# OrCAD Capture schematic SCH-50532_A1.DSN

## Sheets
1 1. TITLE & NOTES: title: X-KTFS5600SKTEVM; rev: A; company: NXP Semiconductors; note: SCH-50532 PDF: SPF-50532; note: 6501 William Cannon Drive West; note: Austin, TX 78735-8598
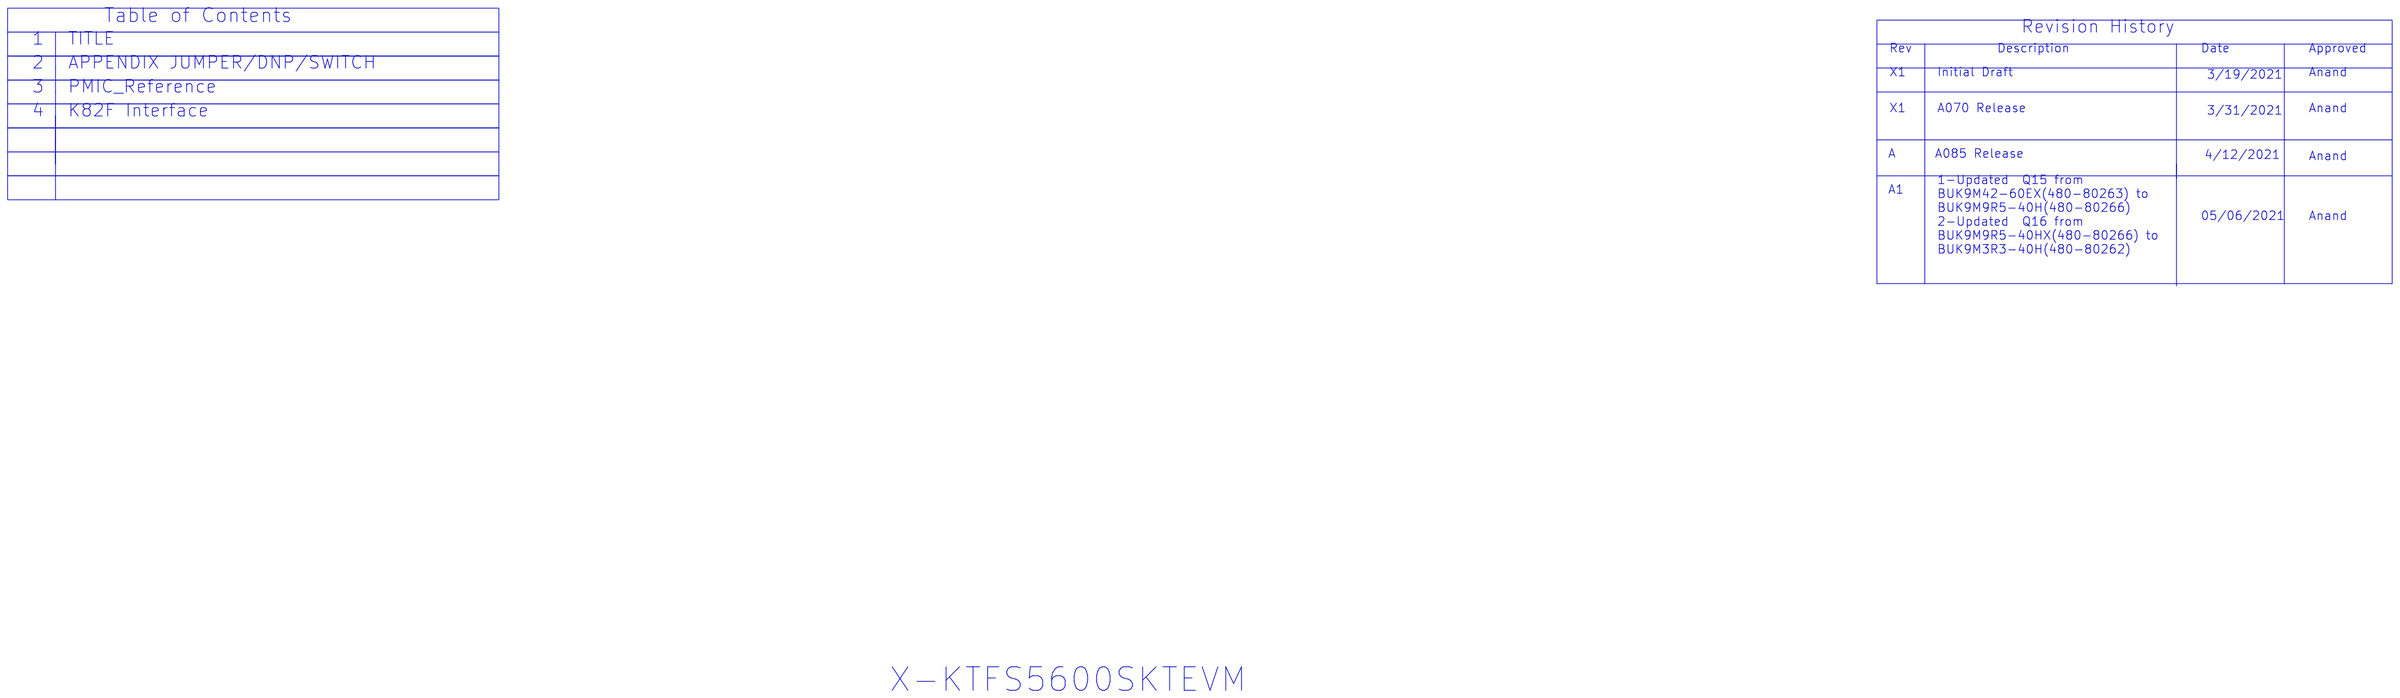
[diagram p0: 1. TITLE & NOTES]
2 3. PMIC_Reference: size D
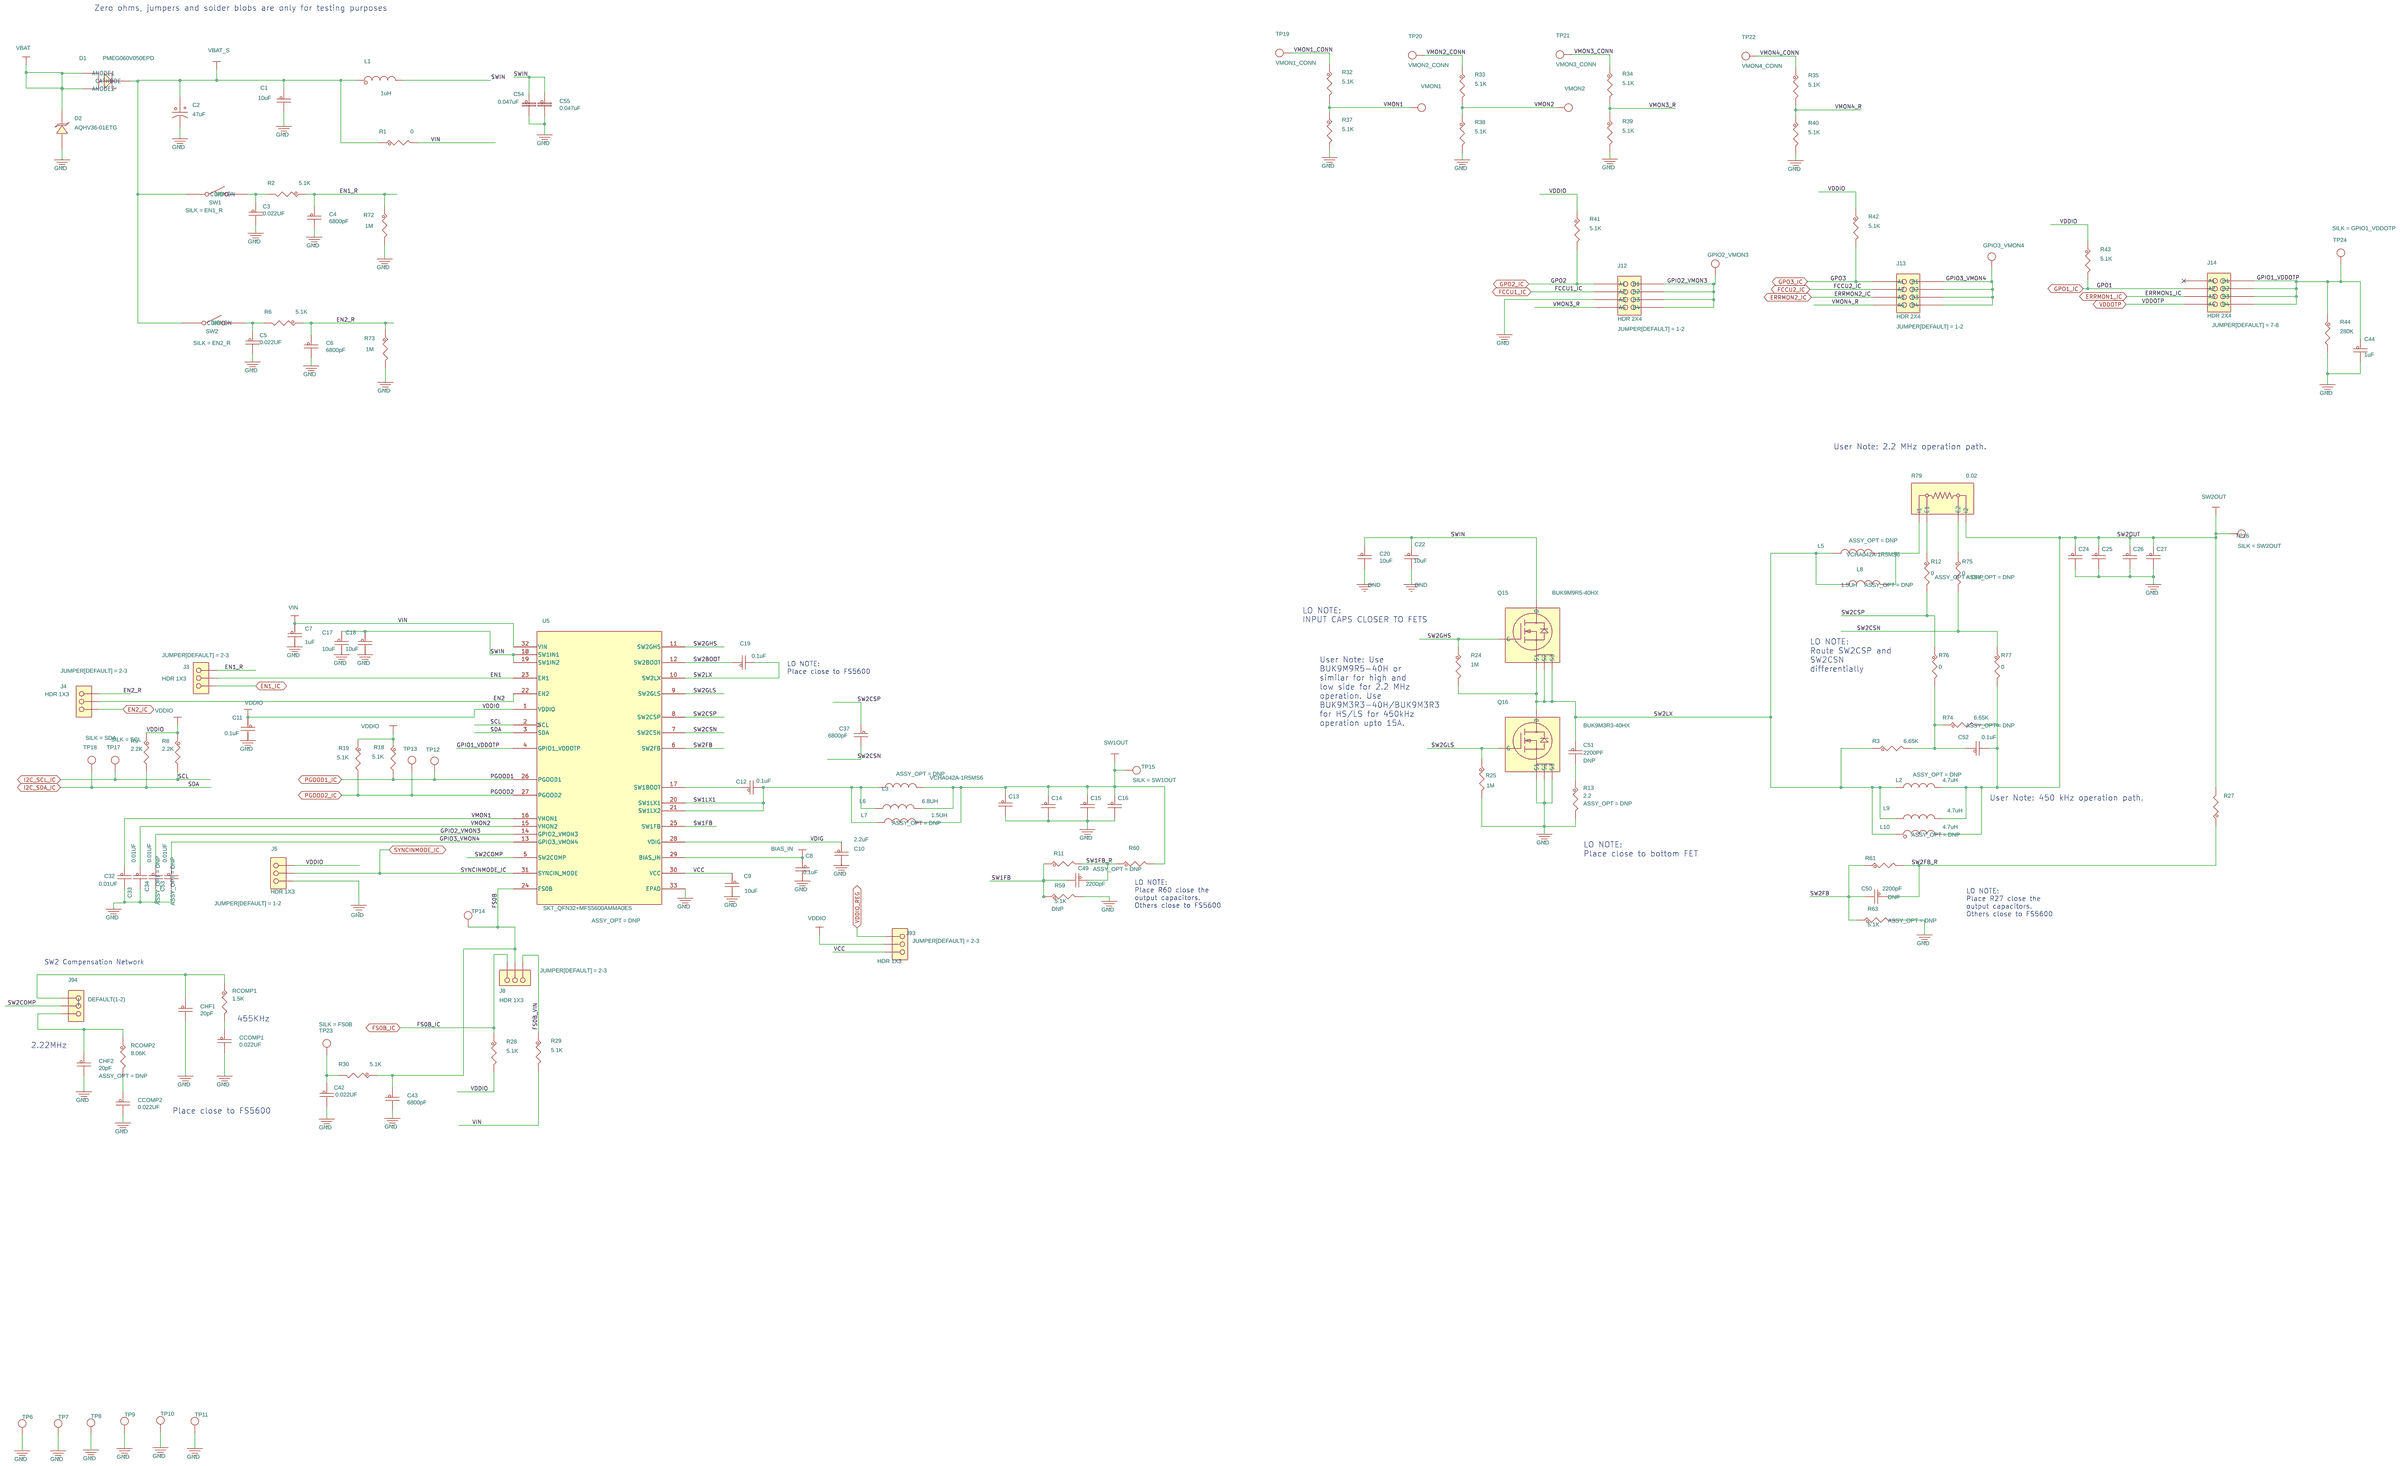
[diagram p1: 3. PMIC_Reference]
3 4. K82F Interface: size C
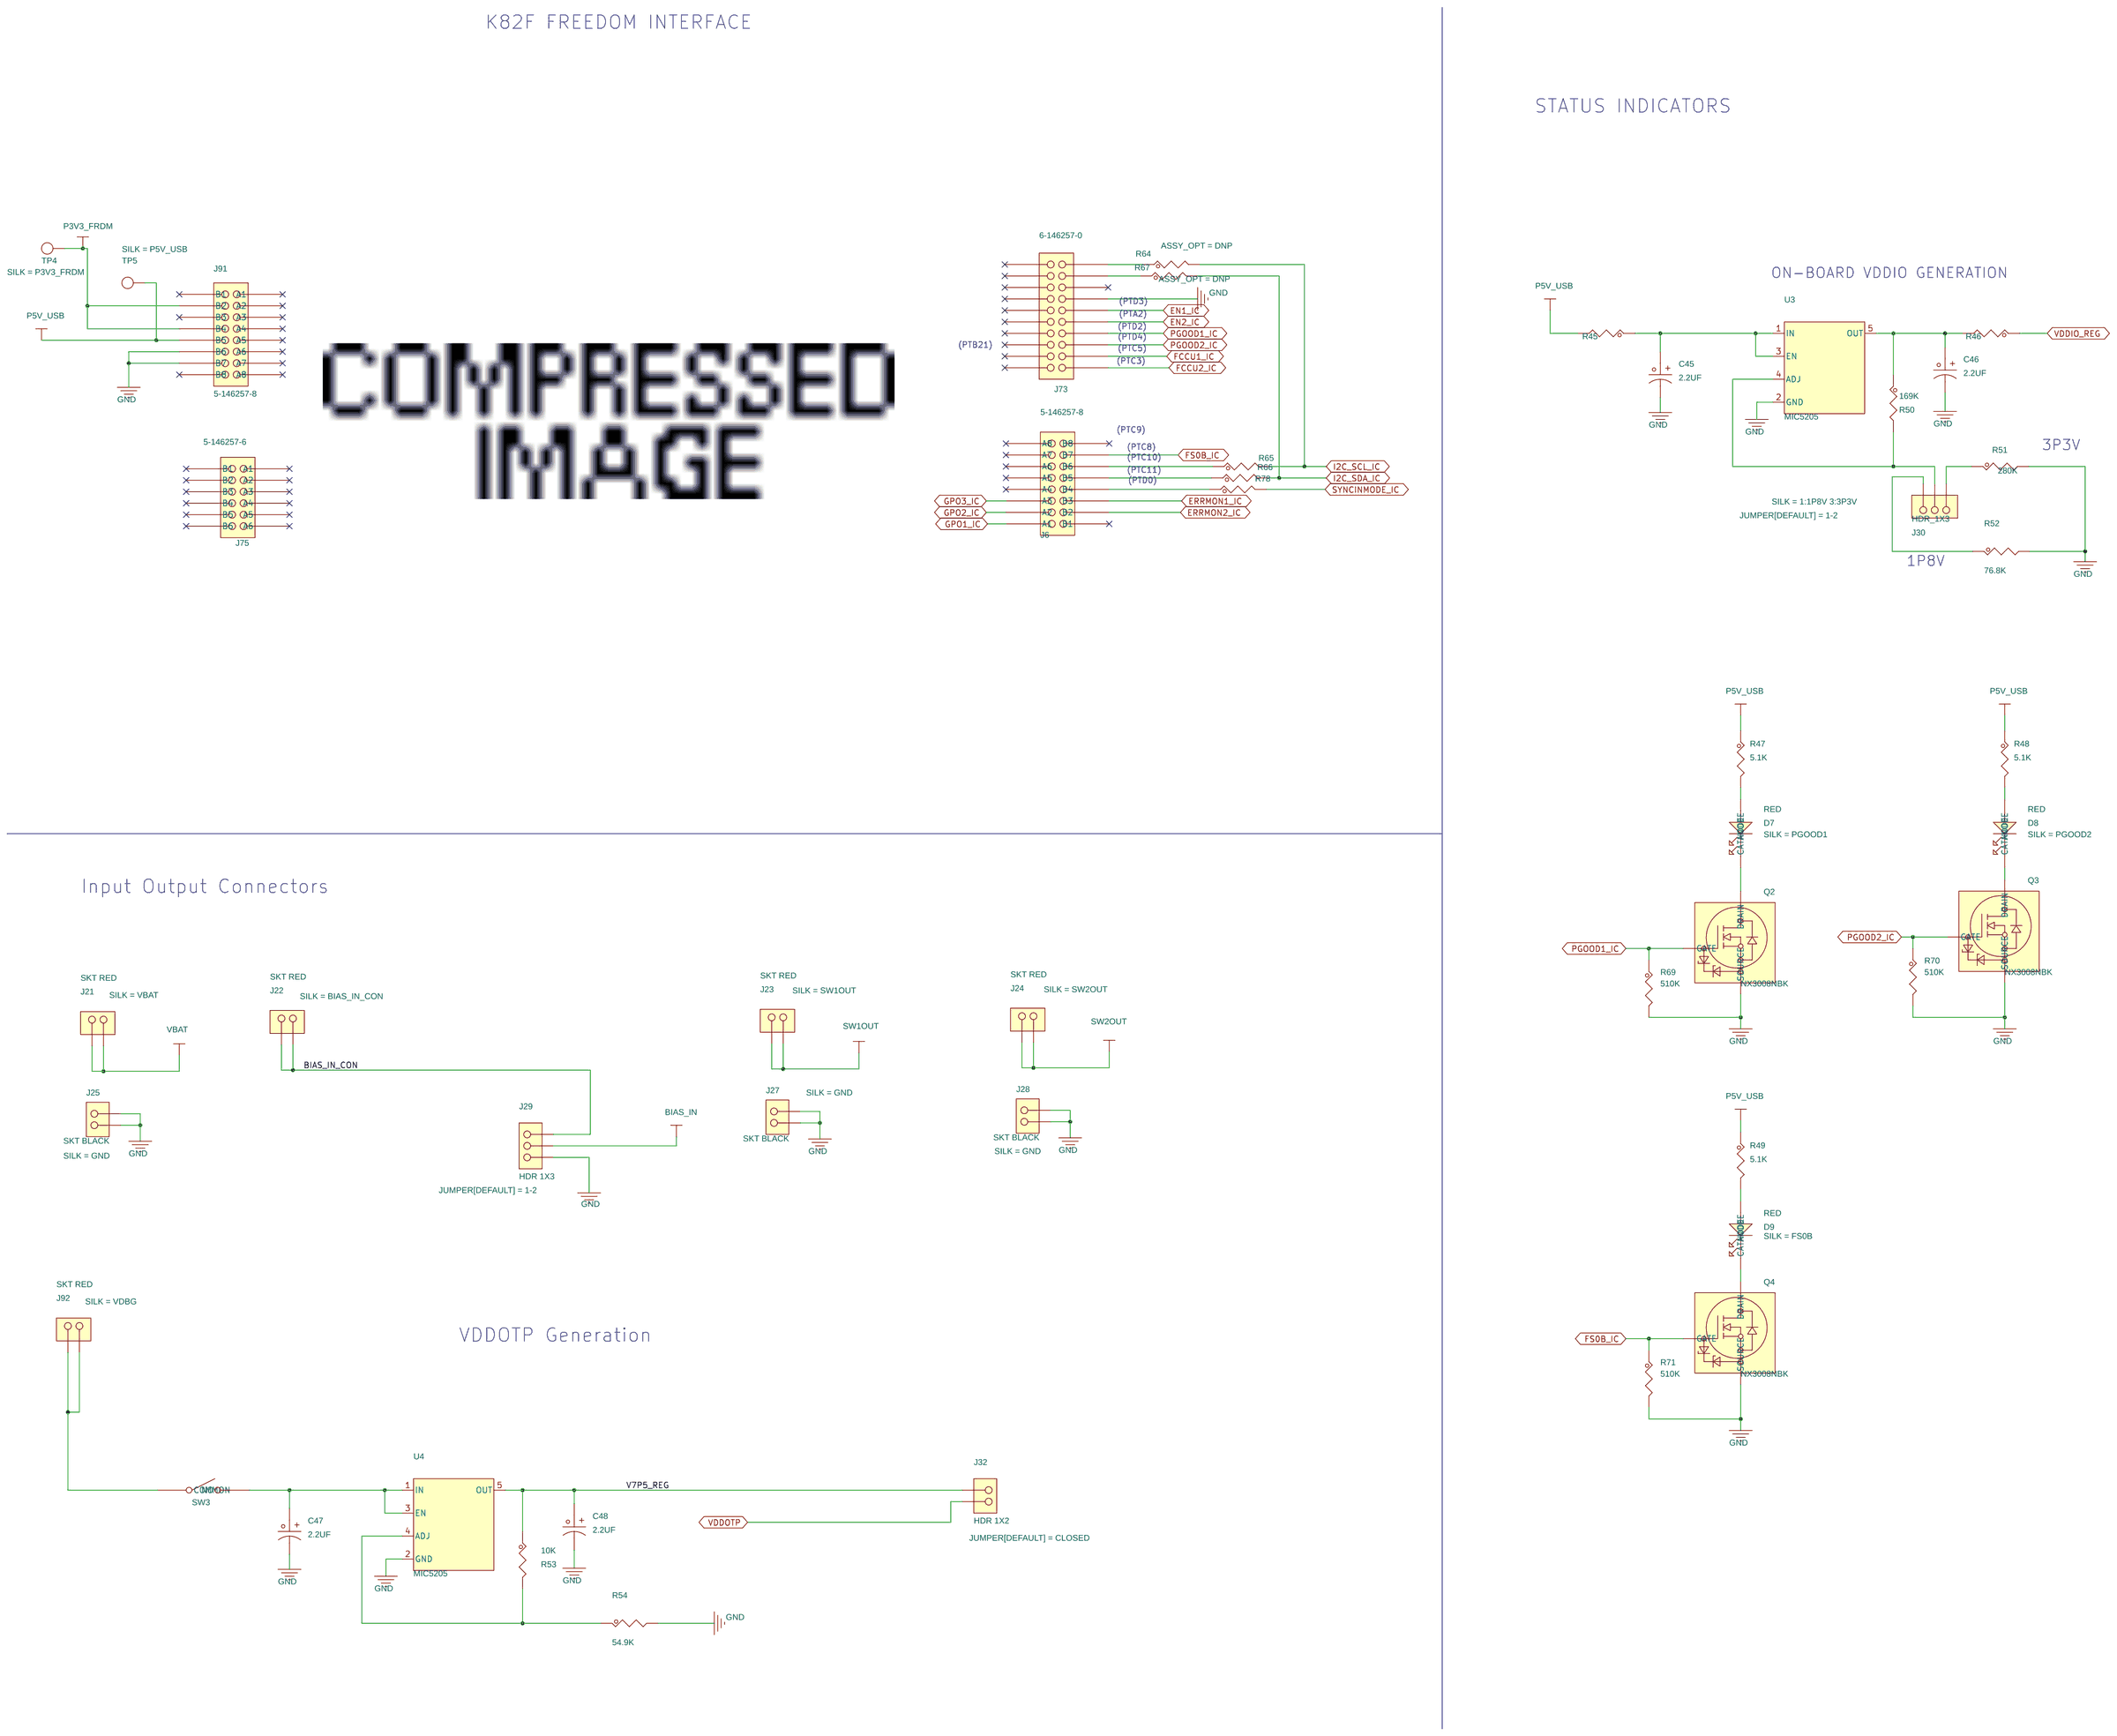
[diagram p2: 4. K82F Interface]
4 2. APPENDIX JUMPER/DNP/SWITCH
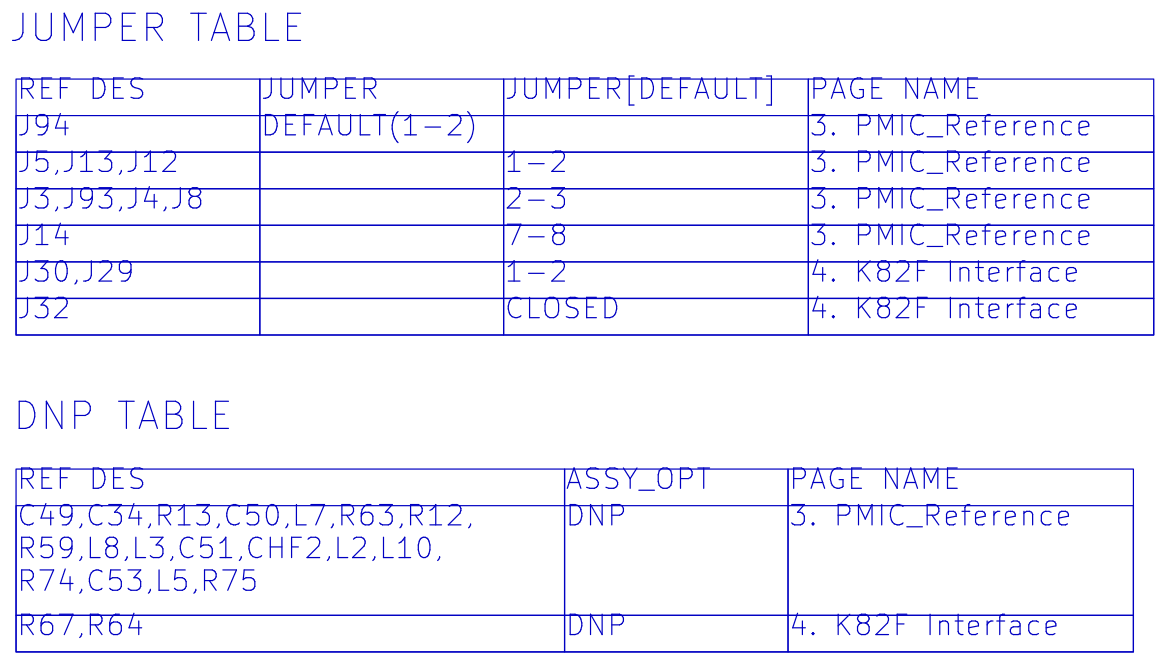
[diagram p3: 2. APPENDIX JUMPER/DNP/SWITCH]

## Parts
sheet 3. PMIC_Reference
C1  10uF  [CC1210]
C2  47uF  [cap_alel_10p5sq_smt]
C3  0.022UF  [CC1206_OV]
C4  6800pF  [CC0402_25]
C5  0.022UF  [CC1206_OV]
C6  6800pF  [CC0402_25]
C7  1uF  [cc0402_tol0p2]
C8  0.1uF  [CC0402_25]
C9  10uF  [CC1210]
C10  2.2uF  [cc0402_tol0p2]
C11  0.1uF  [CC0402_25]
C12  0.1uF  [CC0402_25]
C13  CGA6P1X7R1C226M250AC  [CC1210]
C14  CGA6P1X7R1C226M250AC  [CC1210]
C15  CGA6P1X7R1C226M250AC  [CC1210]
C16  CGA6P1X7R1C226M250AC  [CC1210]
C17  10uF  [CC1210]
C18  10uF  [CC1210]
C19  0.1uF  [CC0402_25]
C20  10uF  [CC1210]
C22  10uF  [CC1210]
C24  CGA6P1X7R1C226M250AC  [CC1210]
C25  CGA6P1X7R1C226M250AC  [CC1210]
C26  CGA6P1X7R1C226M250AC  [CC1210]
C27  CGA6P1X7R1C226M250AC  [CC1210]
C32  0.01UF  [CC0402_25]
C33  0.01UF  [CC0402_25]
C34  0.01UF  [CC0402_25]
C37  6800pF  [CC0402_25]
C42  0.022UF  [CC1206_OV]
C43  6800pF  [CC0402_25]
C44  1uF  [CC0402_25]
C49  2200pF  [CC0402_25]
C50  2200pF  [CC0402_25]
C51  2200PF  [CC0603_OV]
C52  0.1uF  [CC0603_OV]
C53  0.01UF  [CC0402_25]
C54  0.047uF  [cc0204]
C55  0.047uF  [cc0204]
CCOMP1  0.022UF  [CC0603_OV]
CCOMP2  0.022UF  [CC0603_OV]
CHF1  20pF  [CC0603_OV]
CHF2  20pF  [CC0603_OV]
D1  PMEG060V050EPD  [SOT1289]
D2  AQHV36-01ETG  [diode_sod882_sm_0p7x1p1]
GPIO2_VMON3  TPAD_030  [TPAD_030]
GPIO3_VMON4  TPAD_030  [TPAD_030]
J3  HDR 1X3  [HDR103]
J4  HDR 1X3  [HDR103]
J5  HDR 1X3  [HDR103]
J8  HDR 1X3  [HDR103]
J12  HDR 2X4  [hdr2x4_2p54_th]
J13  HDR 2X4  [hdr2x4_2p54_th]
J14  HDR 2X4  [hdr2x4_2p54_th]
J93  HDR 1X3  [HDR103]
J94  HDR 1X3  [HDR103]
L1  1uH  [ind2_7p4x6p9_sm]
L2  4.7uH  [ind2_10p9x10p4]
L3  VCHA042A-1R5MS6  [ind2_4p5x4p3]
L5  VCHA042A-1R5MS6  [ind2_4p5x4p3]
L6  6.8UH  [ind2_10p9x10p4]
L7  1.5UH  [ind_2_5p4x5p8]
L8  1.5UH  [ind_2_5p4x5p8]
L9  4.7uH  [ind2_13p4x12p9mm_sm]
L10  4.7uH  [ind2_7p4x6p9_sm]
Q15  BUK9M9R5-40HX  [lfpak33_0p65_3p4x2p7]
Q16  BUK9M3R3-40HX  [lfpak33_0p65_3p4x2p7]
R1  0  [RC0603_OV]
R2  5.1K  [RC0402_25]
R3  6.65K  [RC0402_25]
R6  5.1K  [RC0402_25]
R8  2.2K  [RC0402_25]
R9  2.2K  [RC0402_25]
R11  0  [RC0402_25]
R12  0  [RC0603_OV]
R13  2.2  [RC0805_OV]
R18  5.1K  [RC0402_25]
R19  5.1K  [RC0402_25]
R24  1M  [RC0402_25]
R25  1M  [RC0402_25]
R27  49.9  [RC0603_OV]
R28  5.1K  [RC0402_25]
R29  5.1K  [RC0402_25]
R30  5.1K  [RC0402_25]
R32  5.1K  [RC0402_25]
R33  5.1K  [RC0402_25]
R34  5.1K  [RC0402_25]
R35  5.1K  [RC0402_25]
R37  5.1K  [RC0402_25]
R38  5.1K  [RC0402_25]
R39  5.1K  [RC0402_25]
R40  5.1K  [RC0402_25]
R41  5.1K  [RC0402_25]
R42  5.1K  [RC0402_25]
R43  5.1K  [RC0402_25]
R44  280K  [RC0402_25]
R59  5.1K  [RC0402_25]
R60  49.9  [RC0603_OV]
R61  0  [RC0402_25]
R63  5.1K  [RC0402_25]
R72  1M  [RC0402_25]
R73  1M  [RC0402_25]
R74  6.65K  [RC0402_25]
R75  0  [RC0603_OV]
R76  0  [RC0603_OV]
R77  0  [RC0603_OV]
R79  0.02  [rc2512_4p_6p6x3p4]
RCOMP1  1.5K  [RC0603_OV]
RCOMP2  8.06K  [RC0603_OV]
SW1  A6S1104-H  [sw2_6p4x3p68_sm]
SW2  A6S1104-H  [sw2_6p4x3p68_sm]
TP6  TESTLOOP  [TEST_PIN_TP107]
TP7  TESTLOOP  [TEST_PIN_TP107]
TP8  TESTLOOP  [TEST_PIN_TP107]
TP9  TESTLOOP  [TEST_PIN_TP107]
TP10  TESTLOOP  [TEST_PIN_TP107]
TP11  TESTLOOP  [TEST_PIN_TP107]
TP12  TESTLOOP_BLACK  [tp_th_063]
TP13  TESTLOOP_BLACK  [tp_th_063]
TP14  TESTLOOP_BLACK  [tp_th_063]
TP15  TESTLOOP_BLACK  [tp_th_063]
TP16  TESTLOOP_BLACK  [tp_th_063]
TP17  TESTLOOP_BLACK  [tp_th_063]
TP18  TESTLOOP_BLACK  [tp_th_063]
TP19  TESTLOOP_BLACK  [tp_th_063]
TP20  TESTLOOP_BLACK  [tp_th_063]
TP21  TESTLOOP_BLACK  [tp_th_063]
TP22  TESTLOOP_BLACK  [tp_th_063]
TP23  TPAD_030  [TPAD_030]
TP24  TPAD_030  [TPAD_030]
U5  SKT_QFN32+MFS5600AMMA0ES  [skt_qfn32_0p5_28x29_sm]
VMON1  TPAD_030  [TPAD_030]
VMON2  TPAD_030  [TPAD_030]
sheet 4. K82F Interface
C45  2.2UF  [CC3216]
C46  2.2UF  [CC3216]
C47  2.2UF  [CC3216]
C48  2.2UF  [CC3216]
D7  RED  [led2_2p1x1p5_nsp]
D8  RED  [led2_2p1x1p5_nsp]
D9  RED  [led2_2p1x1p5_nsp]
J6  5-146257-8  [hdr208_197x789_th]
J21  SKT RED  [con_banana_571]
J22  SKT RED  [con_banana_571]
J23  SKT RED  [con_banana_571]
J24  SKT RED  [con_banana_571]
J25  SKT BLACK  [con_banana_571]
J27  SKT BLACK  [con_banana_571]
J28  SKT BLACK  [con_banana_571]
J29  HDR 1X3  [HDR103]
J30  HDR_1X3  [HDR103]
J32  HDR 1X2  [hdr102_338h]
J73  6-146257-0  [hdr210_197x989_th]
J75  5-146257-6  [hdr206_197x589_th]
J91  5-146257-8  [hdr208_197x789_th]
J92  SKT RED  [con_banana_571]
Q2  NX3008NBK  [SOT23_A]
Q3  NX3008NBK  [SOT23_A]
Q4  NX3008NBK  [SOT23_A]
R45  0  [RC0402_25]
R46  0  [RC0402_25]
R47  5.1K  [RC0402_25]
R48  5.1K  [RC0402_25]
R49  5.1K  [RC0402_25]
R50  169K  [RC0402_25]
R51  280K  [RC0402_25]
R52  76.8K  [RC0402_25]
R53  10K  [RC0402_25]
R54  54.9K  [RC0402_25]
R64  0  [RC0402_25]
R65  0  [RC0402_25]
R66  0  [RC0402_25]
R67  0  [RC0402_25]
R69  510K  [RC0603_OV]
R70  510K  [RC0603_OV]
R71  510K  [RC0603_OV]
R78  0  [RC0402_25]
SW3  A6S1104-H  [sw2_6p4x3p68_sm]
TP4  TPAD_030  [TPAD_030]
TP5  TPAD_030  [TPAD_030]
U3  MIC5205  [sot23-20x60-5]
U4  MIC5205  [sot23-20x60-5]

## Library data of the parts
C1 C9 C17 C18 C20 C22 = CAP_NP: CAP CER 10uF 50V 10% X7S AEC-Q200 1210; AGILE_PN: 150-79213; CAD_APPROVED: Yes; FPLIST: CC1210,1210_CC; HEIGHT: 2.8MM; MFG_NAME01: MURATA; MFG_PN01: GCM32EC71H106KA03; Package Size: 1210; ROHS: Yes; Tolerance: 10%; VOLTAGE: 50V
C2 = CAP_POL: CAP ALEL 47uF 50V 20% AEC-Q200 SMD; AGILE_PN: 150-79431; CAD_APPROVED: Yes; HEIGHT: 10.5MM; MFG_NAME01: VISHAY INTERTECHNOLOGY; MFG_PN01: MAL214699101E3; ROHS: Yes; Tolerance: 20%; VOLTAGE: 50V
C3 C5 C42 = CAP_NP: CAP CER 0.022UF 100V 10% X7R 1206; AGILE_PN: 150-76992; CAD_APPROVED: Yes; FPLIST: CC1206_OV,CC1206,1206_CC; HEIGHT: 0.94MM; MFG_NAME01: AVX; MFG_PN01: 12061C223KAT2A; Package Size: 1206; ROHS: Yes; Tolerance: 10%; VOLTAGE: 100V
C4 C6 C37 C43 = CAP_NP: CAP CER 6800PF 50V 10% X7R 0402; AGILE_PN: 150-77502; CAD_APPROVED: Yes; FPLIST: CC0402_25,CC0402_HD,0402_CC; HEIGHT: 0.55 MM; MFG_NAME01: KEMET; MFG_PN01: C0402C682K5RAC_; Package Type: 0402; ROHS: Yes; Tolerance: 10%; VOLTAGE: 50V
C7 = CAP_NP: CAP CER 1uF 10V 10% X7S AEC-Q200 0402; AGILE_PN: 150-79497; CAD_APPROVED: Yes; FPLIST: CC0402_25,CC0402_HD,0402_CC; HEIGHT: 0.7MM; MFG_NAME01: MURATA; MFG_PN01: GCM155C71A105KE38D; Package Size: 0402; ROHS: Yes; Tolerance: 10%; VOLTAGE: 10V
C8 C11 = CAP_NP: CAP CER 0.1uF 50V 10% X7R AEC-Q200 0402; AGILE_PN: 150-79461; CAD_APPROVED: Yes; FPLIST: CC0402_25,CC0402_HD,0402_CC; HEIGHT: 0.55MM; MFG_NAME01: MURATA; MFG_PN01: GCM155R71H104KE02D; Package Size: 0402; ROHS: Yes; Tolerance: 10%; VOLTAGE: 50V
C10 = CAP_NP: CAP CER 2.2uF 10V 10% X7S AEC-Q200 0402; AGILE_PN: 150-79885; CAD_APPROVED: Yes; FPLIST: CC0402_25,CC0402_HD,0402_CC; HEIGHT: 0.7MM; MFG_NAME01: MURATA; MFG_PN01: GRT155C71A225KE13; ROHS: Yes; Temp Range: -55°C to +125°C; Tolerance: 10%; VOLTAGE: 10 V
C12 C19 = CAP_NP: CAP CER 0.1uF 50V 10% X7R AEC-Q200 0402; AGILE_PN: 150-79461; CAD_APPROVED: Yes; FPLIST: CC0402_25,CC0402_HD,0402_CC,CC0402_18; HEIGHT: 0.55MM; MFG_NAME01: MURATA; MFG_PN01: GCM155R71H104KE02D; Package Size: 0402; ROHS: Yes; Tolerance: 10%; VOLTAGE: 50V
C13-C16 C24-C27 = CAP_NP: CAP CER 22uF 16V 20% X7R AEC-Q200 1210; AGILE_PN: 150-80303; CAD_APPROVED: Yes; FPLIST: CC1210,1210_CC; HEIGHT: 2.8MM; MFG_NAME01: TDK; Package Type: 1210; ROHS: Yes; Temp Range: &#8722;55°C to +125°C; Tolerance: 10%; VOLTAGE: 16V
C32 C33 = CAP_NP: CAP CER 0.01UF 10V 20% X7R 0402; AGILE_PN: 150-30081; CAD_APPROVED: Yes; FPLIST: CC0402_25,CC0402_HD,0402_CC,capc0402_l; HEIGHT: 0.56 MM; MFG_NAME01: AVX; MFG_PN01: 0402ZC103MAT2A; Package Size: 0402; ROHS: Yes; Tolerance: 20%; VOLTAGE: 10V
C34 C53 = CAP_NP: CAP CER 0.01UF 10V 20% X7R 0402; AGILE_PN: 150-30081; ASSY_OPT: DNP; CAD_APPROVED: Yes; FPLIST: CC0402_25,CC0402_HD,0402_CC,capc0402_l; HEIGHT: 0.56 MM; MFG_NAME01: AVX; MFG_PN01: 0402ZC103MAT2A; Package Size: 0402; ROHS: Yes; Tolerance: 20%; VOLTAGE: 10V
C44 = CAP_NP: CAP CER 1.0uF 16V 10% X6S 0402; AGILE_PN: 150-80262; CAD_APPROVED: Yes; FPLIST: CC0402_25,CC0402_HD,0402_CC; HEIGHT: 0.55MM; MFG_NAME01: MURATA; MFG_PN01: GRM155C81C105KE11D; ROHS: Yes; Temp Range: -55°C to +105°C; Temp_Range: -55°C to +105°C; Tolerance: 10%; VOLTAGE: 16V
C49 C50 = CAP_NP: CAP CER 2200pF 50V 10% X7R AEC-Q200 0402; AGILE_PN: 150-79020; ASSY_OPT: DNP; CAD_APPROVED: Yes; FPLIST: CC0402_25,CC0402_HD,0402_CC; HEIGHT: 0.55MM; MFG_NAME01: MURATA; MFG_PN01: GCM155R71H222KA37D; Package Size: 0402; Package Type: ø180mm Reel PAPER; ROHS: Yes; Tolerance: 10%; VOLTAGE: 50V
C51 = CAP_NP: CAP CER 2200PF 50V 10% X7R 0603; AGILE_PN: 150-75275; ASSY_OPT: DNP; CAD_APPROVED: Yes; FPLIST: CC0603_OV,CC0603,0603_CC; HEIGHT: 0.9652MM; MFG_NAME01: AVX; MFG_PN01: 06035C222KAT2A; Package Size: 0603; Package Type: paper tape; ROHS: Yes; Tolerance: 10%; VOLTAGE: 50V
C52 = CAP_NP: CAP CER 0.1uF 50V 5% X7R AEC-Q200 0603; AGILE_PN: 150-79363; CAD_APPROVED: Yes; HEIGHT: 0.87MM; MFG_NAME01: KEMET; MFG_PN01: C0603C104J5RACAUTO; Package Size: 0603; Package Type: 7" Reel; ROHS: Yes; Temp Range: -55°C to +125°C; Tolerance: 5%; VOLTAGE: 50V
C54 C55 = CAP_NP_RVRS: CAP CER 0.047 uF 50V 20% X7R AEC-Q200 0204; AGILE_PN: 180-81030; CAD_APPROVED: Yes; HEIGHT: 0.35MM; MFG_NAME01: TDK Corporation; MFG_PN01: CGAEA1X7R1H473M030BC; Package Size: 0204 (0510 Metric); Package Type: Surface Mount, MLCC; ROHS: yes; Rated Voltage: 50V; Tolerance: 20%; VOLTAGE: 50V
CCOMP1 CCOMP2 = CAP_NP: CAP CER 0.022UF 50V 5% X7R 0603; AGILE_PN: 150-77536; CAD_APPROVED: Yes; FPLIST: CC0603_OV,CC0603,0603_CC; HEIGHT: 0.9MM; MFG_NAME01: KEMET; MFG_PN01: C0603C223J5RACTU; Package Size: 0603; ROHS: Yes; Tolerance: 5%; VOLTAGE: 50V
CHF1 = CAP_NP: CAP CER 20pF 50V C0G 1% 0603; AGILE_PN: 150-80878; CAD_APPROVED: Yes; FPLIST: CC0603_OV,CC0603,0603_CC; HEIGHT: 0.87MM; MFG_NAME01: KEMET; MFG_PN01: C0603C200F5GACTU; Package Size: 0603 (1608 metric); Package Type: SMD/SMT; ROHS: Yes; Rated Voltage: 50VDC; Temp Range: -55 °C to +125 °C; Tolerance: 1%
CHF2 = CAP_NP: CAP CER 20pF 50V C0G 1% 0603; AGILE_PN: 150-80878; ASSY_OPT: DNP; CAD_APPROVED: Yes; FPLIST: CC0603_OV,CC0603,0603_CC; HEIGHT: 0.87MM; MFG_NAME01: KEMET; MFG_PN01: C0603C200F5GACTU; Package Size: 0603 (1608 metric); Package Type: SMD/SMT; ROHS: Yes; Rated Voltage: 50VDC; Temp Range: -55 °C to +125 °C; Tolerance: 1%
D1 = DIODE_SCH_A1A2C3: DIODE SCH RECT 60V 5A AEC-Q101 SOT1289; AGILE_PN: 480-78888; CAD_APPROVED: Yes; HEIGHT: 0.82MM; MFG_NAME01: NEXPERIA; ROHS: Yes; VOLTAGE: 60V
D2 = DIODE_TVS: DIODE TVS UNIDIR 36V -- AEC-Q101 SOD882; AGILE_PN: 480-80142; CAD_APPROVED: Yes; HEIGHT: 0.6MM; MFG_NAME01: LITTELFUSE; REQUESTED_COMPLETION_DATE: Not an expedite request; ROHS: Yes; Temp Range: -40C to +150C; Temp_Range: -40C to +150C
GPIO2_VMON3 GPIO3_VMON4 VMON1 VMON2 = TestLoop: TEST POINT PAD 30MIL DIA SMT, NO PART TO ORDER; 3D_Mechanical_Footprint_File: ftp://fcl.am.freescale.net/ALLEGRO/step/tpad_030.STEP; AGILE_PN: 211-76642; CAD_APPROVED: Yes; HEIGHT: 0.1MM; MFG_NAME01: NOTACOMPONENT; MFG_PN01: NOTACOMPONENT; ROHS: Yes
J3 J4 J8 J93 = CONN_HDR_3X1: HDR 1x3 TH 100MIL SP 343H SN 100L; AGILE_PN: 210-80334; CAD_APPROVED: Yes; HEIGHT: 8.72MM; JUMPER[DEFAULT]: 2-3; MFG_NAME01: SAMTEC; MFG_PN01: TSW-103-07-T-S; ROHS: Yes
J5 J29 = CONN_HDR_3X1: HDR 1x3 TH 100MIL SP 343H SN 100L; AGILE_PN: 210-80334; CAD_APPROVED: Yes; HEIGHT: 8.72MM; JUMPER[DEFAULT]: 1-2; MFG_NAME01: SAMTEC; MFG_PN01: TSW-103-07-T-S; ROHS: Yes
J12 J13 = CONN_HDR_4X2: HDR 2X4 TH 100MIL CTR 344H AU 118L; 3D_Mechanical_Footprint_File: ftp://fcl.am.freescale.net/ALLEGRO/step/hdr2x4_2p54_th.STEP; AGILE_PN: 210-81937; CAD_APPROVED: Yes; HEIGHT: 8.74MM; JUMPER[DEFAULT]: 1-2; MFG_NAME01: WURTH ELEKTRONIK EISOS GMBH & CO. KG (ELECTRONIC & ELECTROMEHANICAL COMP); MFG_PN01: 61300821121; Package Type: TH; ROHS: Yes; Temp Range: -40 to 105C
J14 = CONN_HDR_4X2: HDR 2X4 TH 100MIL CTR 344H AU 118L; 3D_Mechanical_Footprint_File: ftp://fcl.am.freescale.net/ALLEGRO/step/hdr2x4_2p54_th.STEP; AGILE_PN: 210-81937; CAD_APPROVED: Yes; HEIGHT: 8.74MM; JUMPER[DEFAULT]: 7-8; MFG_NAME01: WURTH ELEKTRONIK EISOS GMBH & CO. KG (ELECTRONIC & ELECTROMEHANICAL COMP); MFG_PN01: 61300821121; Package Type: TH; ROHS: Yes; Temp Range: -40 to 105C
J94 = CONN_HDR_3X1: HDR 1x3 TH 100MIL SP 343H SN 100L; AGILE_PN: 210-80334; CAD_APPROVED: Yes; HEIGHT: 8.72MM; JUMPER: DEFAULT(1-2); MFG_NAME01: SAMTEC; MFG_PN01: TSW-103-07-T-S; ROHS: Yes
L1 = INDP: IND PWR 1.0uH@100KHz 17.9A 20% AEC-Q200 SMD; AGILE_PN: 180-78579; CAD_APPROVED: Yes; HEIGHT: 4.5MM; MFG_NAME01: TDK; MFG_PN01: SPM6545VT-1R0M-D; PART_TYPE: INDUCTOR\POWER; ROHS: Yes; Temp Range: -55ºC ~ +150ºC; Temp_Range: -55ºC ~ +150ºC; Tolerance: 20%
L2 = INDUCTOR: IND PWR  4.7uH@100KHz 19.3A 20% AEC-Q200 SMD; 3D_Mechanical_Footprint_File: ftp://fcl.am.freescale.net/ALLEGRO/step/ind2_10p9x10p4.STEP; AGILE_PN: 180-78581; ASSY_OPT: DNP; CAD_APPROVED: Yes; HEIGHT: 6.5MM; MFG_NAME01: TDK; MFG_PN01: SPM10065VT-4R7M-D; ROHS: Yes; Temp Range: -55C to 150C
L3 L5 = INDUCTOR: IND PWR 1.5uH@100kHZ 7.3A 20% AEC-Q200 SMD; AGILE_PN: 180-78991; ASSY_OPT: DNP; CAD_APPROVED: Yes; HEIGHT: 2.1 MM; MFG_NAME01: CYNTEC; PART_TYPE: INDUCTOR\POWER; ROHS: Yes; Temp Range: -55 to 165 C; Tolerance: 20%
L6 = INDUCTOR: IND PWR  6.8uH@100KHz 10.2A 20% AEC-Q200 SMT; 3D_Mechanical_Footprint_File: ftp://fcl.am.freescale.net/ALLEGRO/step/ind2_10p9x10p4.STEP; AGILE_PN: 180-79064; CAD_APPROVED: Yes; HEIGHT: 6.5MM; MFG_NAME01: TDK; MFG_PN01: SPM10065VT-6R8M-D; Package Size: 10.9x10.4x6.5 mm; ROHS: Yes; Temp Range: -55°C to +155°C
L7 L8 = INDUCTOR: IND PWR 1.5UH@100kHZ 7.9A 20% AEC-Q200 SMT; 3D_Mechanical_Footprint_File: ftp://fcl.am.freescale.net/ALLEGRO/step/ind2_5p9x5p4_3_sm.STEP; AGILE_PN: 180-79063; ASSY_OPT: DNP; CAD_APPROVED: Yes; HEIGHT: 3.0MM; MFG_NAME01: TDK Corporation; MFG_PN01: SPM5030VT-1R5M-D; ROHS: Yes; Temp Range: -55ºC ~ +155ºC
L9 = INDUCTOR: IND PWR 4.7uH@100KHz 14.0A 20% AEC-Q200 SMT; AGILE_PN: 180-79532; CAD_APPROVED: Yes; HEIGHT: 6.5MM; MFG_NAME01: TDK Corporation; MFG_PN01: SPM12565VT-4R7M-D; ROHS: Yes; Temp Range: -55C to +155C
L10 = INDP: IND PWR 4.7uH@100kHz 10.9A 20% AEC-Q200 SMT; AGILE_PN: 180-78917; ASSY_OPT: DNP; CAD_APPROVED: Yes; HEIGHT: 4.5 MM; MFG_NAME01: TDK; MFG_PN01: SPM6545VT- 4R7M-D; ROHS: Yes; Temp Range: -55ºC to +155ºC
Q15 = NMOS_5P: TRAN NMOS PWR 40A 40V 9.5mOHM AEC-Q101 LFPAK33; AGILE_PN: 480-80266; CAD_APPROVED: YES; HEIGHT: 0.9MM; MFG_NAME01: Nexperia USA Inc.; Package Size: SOT-1210, 8-LFPAK33 (5-Lead); ROHS: YES; Rated Power: 55W (Ta); Temp Range: -55°C ~ +175°C
Q16 = NMOS_5P: TRAN NMOS PWR 40V 80A AEC-Q101 LFPAK33; AGILE_PN: 480-80262; CAD_APPROVED: Yes; HEIGHT: 0.9MM; MFG_NAME01: Nexperia; Package Size: SOT-1210, 8-LFPAK33 (5-Lead); ROHS: Yes; Rated Power: 101W (Ta); Temp Range: -55C to +175C
R1 = RES: RES MF ZERO OHM 1/10W -- 0603; AGILE_PN: 470-80866; CAD_APPROVED: Yes; FPLIST: RC0603_OV,RC0603,R603-X2,0603_CC; HEIGHT: 0.6MM; MFG_NAME01: YAGEO AMERICA; MFG_PN01: RC0603FR-070RL; ROHS: Yes; Temp Range: –55 °C to +155 °C; Temp_Range: –55 °C to +155 °C
R2 R6 R18 R19 R28-R30 R32-R35 R37-R43 R47-R49 = RES: RES MF 5.1K 1/16W 0.1% 0402; AGILE_PN: 470-80361; CAD_APPROVED: Yes; FPLIST: RC0603_OV,RC0603,0603_CC; HEIGHT: 0.4MM; MFG_NAME01: PANASONIC; MFG_PN01: ERA2AEB512X; ROHS: Yes; TOL: 5%; Tolerance: 0.1%
R3 = RES: RES MF 6.65K 1/16W 1% 0402; AGILE_PN: 470-82718; CAD_APPROVED: Yes; FPLIST: RC0402_25,RC0402_HD,0402_CC; HEIGHT: 0.35 MM; MFG_NAME01: Vishay / Dale; MFG_PN01: CRCW04026K65FKEDC; Package Type: PCB Mount; ROHS: Yes; Temp Range: -55°C ~ 155°C; Tolerance: 1%
R8 R9 = RES: RES MF 2.2K 1/10W 1% AEC-Q200 0402; AGILE_PN: 470-82015; CAD_APPROVED: Yes; FPLIST: RC0402_25,RC0402_HD,0402_CC; HEIGHT: 0.4MM; MFG_NAME01: KOA SPEER; MFG_PN01: RK73H1ETTP2201F; ROHS: Yes; TOL: 5%; Temp Coefficient - ppm/K: 100 ppm/K; Temp Range: -55C to +155C; Tolerance: 1%; VOLTAGE: 50V
R11 R45 R46 R61 R65 R66 R78 = RES: RES MF ZERO OHM 1/16W -- AEC-Q200 0402; AGILE_PN: 470-80742; CAD_APPROVED: Yes; FPLIST: RC0402_25,RC0402_HD,0402_CC; HEIGHT: 0.45 MM; MFG_NAME01: VISHAY INTERTECHNOLOGY; MFG_PN01: CRCW04020000Z0ED; ROHS: Yes
R12 R75 = RES: RES MF ZERO OHM 1/10W -- 0603; AGILE_PN: 470-80866; ASSY_OPT: DNP; CAD_APPROVED: Yes; FPLIST: RC0603_OV,RC0603,R603-X2,0603_CC; HEIGHT: 0.6MM; MFG_NAME01: YAGEO AMERICA; MFG_PN01: RC0603FR-070RL; ROHS: Yes; Temp Range: –55 °C to +155 °C
R13 = RES: RES MF 2.2 OHM 1/3W 5% AEC-Q200 0805; AGILE_PN: 470-80816; ASSY_OPT: DNP; CAD_APPROVED: Yes; HEIGHT: 0.6MM; MFG_NAME01: VISHAY INTERTECHNOLOGY; MFG_PN01: CRCW08052R20JNEAHP; ROHS: Yes; Tolerance: 5%
R24 R25 R72 R73 = RES: RES MF 1.0M 1/16W 1% AEC-Q200 0402; AGILE_PN: 470-30000; CAD_APPROVED: Yes; FPLIST: RC0402_25,RC0402_HD,0402_CC; HEIGHT: 0.4MM; MFG_NAME01: VISHAY INTERTECHNOLOGY; MFG_PN01: CRCW04021M00FKED; PRIORITY_PN: 006-00757; ROHS: Yes; Temp Coefficient - ppm/K: ±100ppm/°C; Temp Range: -55°C ~ 155°C; Temp_Range: -55°C ~ 155°C; Tolerance: 1%; VOLTAGE: 50V
R27 R60 = RES: RES MF 49.9 OHM 1/10W 1% 0603; AGILE_PN: 470-75432; CAD_APPROVED: Yes; FPLIST: RC0603_OV,RC0603,0603_CC; HEIGHT: 0.55 MM; MFG_NAME01: BOURNS; MFG_PN01: CR0603-FX-49R9ELF; ROHS: Yes; Tolerance: 1%
R44 R51 = RES: RES MF 280K 1/10W 1% AEC-Q200 0402; AGILE_PN: 470-31109; CAD_APPROVED: Yes; FPLIST: RC0402_25,RC0402_HD,0402_CC; HEIGHT: 0.40 MM; MFG_NAME01: KOA SPEER; MFG_PN01: RK73H1ETTP2803F; ROHS: Yes; Temp Coefficient - ppm/K: 100 ppm/K; Temp Range: -55C to +155C; Temp_Range: -55C to +155C; Tolerance: 1%; VOLTAGE: 50V
R59 R63 = RES: RES MF 5.1K 1/16W 0.1% 0402; AGILE_PN: 470-80361; ASSY_OPT: DNP; CAD_APPROVED: Yes; FPLIST: RC0603_OV,RC0603,0603_CC; HEIGHT: 0.4MM; MFG_NAME01: PANASONIC; MFG_PN01: ERA2AEB512X; ROHS: Yes; TOL: 5%; Tolerance: 0.1%
R74 = RES: RES MF 6.65K 1/16W 1% 0402; AGILE_PN: 470-82718; ASSY_OPT: DNP; CAD_APPROVED: Yes; FPLIST: RC0402_25,RC0402_HD,0402_CC; HEIGHT: 0.35 MM; MFG_NAME01: Vishay / Dale; MFG_PN01: CRCW04026K65FKEDC; Package Type: PCB Mount; ROHS: Yes; Temp Range: -55°C ~ 155°C; Tolerance: 1%
R76 R77 = RES: RES MF ZERO OHM 1/10W -- 0603; AGILE_PN: 470-80866; CAD_APPROVED: Yes; FPLIST: RC0603_OV,RC0603,R603-X2,0603_CC; HEIGHT: 0.6MM; MFG_NAME01: YAGEO AMERICA; MFG_PN01: RC0603FR-070RL; ROHS: Yes; Temp Range: –55 °C to +155 °C
R79 = RES_4PIN: RES MF 0.02 OHM 1W 1% AEC-Q200 2512; AGILE_PN: 470-82632; CAD_APPROVED: Yes; HEIGHT: 0.9MM; MFG_NAME01: VISHAY; MFG_PN01: WSK2512R0200FEA; Package Size: 2512; Package Type: SMD/SMT; ROHS: Yes; Temp Range: -65C to +170C; Tolerance: 1%
RCOMP1 = RES: RES MF 1.5K 1/10W 5% 0603; AGILE_PN: 470-75995; CAD_APPROVED: YES; FPLIST: RC0603_OV,RC0603,0603_CC; HEIGHT: 0.55 MM; MFG_NAME01: BOURNS; MFG_PN01: CR0603-JW-152ELF; ROHS: Yes; Tolerance: 5%
RCOMP2 = RES: RES MF 8.06K 1/10W 1% AEC-Q200 0603; AGILE_PN: 470-81280; CAD_APPROVED: Yes; FPLIST: RC0603_OV,RC0603,0603_CC; HEIGHT: 0.55MM; MFG_NAME01: KOA SPEER; MFG_PN01: RK73H1JTTD8061F; ROHS: Yes; Temp Range: -55°C to +155°C; Tolerance: 1%
SW1 = SW2P: SW SPST DIP SLD 25mA 24V SMD; AGILE_PN: 510-78107; CAD_APPROVED: Yes; HEIGHT: 4.5MM; MFG_NAME01: OMRON; MFG_PN01: A6S-1104-H; ROHS: Yes; SILK: EN1_R; VOLTAGE: 24V
SW2 = SW2P: SW SPST DIP SLD 25mA 24V SMD; AGILE_PN: 510-78107; CAD_APPROVED: Yes; HEIGHT: 4.5MM; MFG_NAME01: OMRON; MFG_PN01: A6S-1104-H; ROHS: Yes; SILK: EN2_R; VOLTAGE: 24V
TP6-TP11 = TestLoop: TEST POINT PAD SIZE 4.7MM X 3.5MM SN; 3D_Mechanical_Footprint_File: ftp://fcl.am.freescale.net/ALLEGRO/step/TEST_PIN_TP107.STEP; AGILE_PN: 211-30043; CAD_APPROVED: Yes; HEIGHT: 2.286MM; MFG_NAME01: KEYSTONE ELECTRONICS; MFG_PN01: 5016; PRIORITY_PN: 028-00650; ROHS: Yes; Temp Range: -50°C to +146°C
TP12-TP14 = TestLoop: TEST POINT PC MULTI PURPOSE BLK TH; 3D_Mechanical_Footprint_File: ftp://fcl.am.freescale.net/ALLEGRO/step/tp_th_063.STEP; AGILE_PN: 210-79450; CAD_APPROVED: Yes; HEIGHT: 8.13MM; MFG_NAME01: KEYSTONE ELECTRONICS; MFG_PN01: 5011; ROHS: Yes
TP15 = TestLoop: TEST POINT PC MULTI PURPOSE BLK TH; 3D_Mechanical_Footprint_File: ftp://fcl.am.freescale.net/ALLEGRO/step/tp_th_063.STEP; AGILE_PN: 210-79450; CAD_APPROVED: Yes; HEIGHT: 8.13MM; MFG_NAME01: KEYSTONE ELECTRONICS; MFG_PN01: 5011; ROHS: Yes; SILK: SW1OUT
TP16 = TestLoop: TEST POINT PC MULTI PURPOSE BLK TH; 3D_Mechanical_Footprint_File: ftp://fcl.am.freescale.net/ALLEGRO/step/tp_th_063.STEP; AGILE_PN: 210-79450; CAD_APPROVED: Yes; HEIGHT: 8.13MM; MFG_NAME01: KEYSTONE ELECTRONICS; MFG_PN01: 5011; ROHS: Yes; SILK: SW2OUT
TP17 = TestLoop: TEST POINT PC MULTI PURPOSE BLK TH; 3D_Mechanical_Footprint_File: ftp://fcl.am.freescale.net/ALLEGRO/step/tp_th_063.STEP; AGILE_PN: 210-79450; CAD_APPROVED: Yes; HEIGHT: 8.13MM; MFG_NAME01: KEYSTONE ELECTRONICS; MFG_PN01: 5011; ROHS: Yes; SILK: SCL
TP18 = TestLoop: TEST POINT PC MULTI PURPOSE BLK TH; 3D_Mechanical_Footprint_File: ftp://fcl.am.freescale.net/ALLEGRO/step/tp_th_063.STEP; AGILE_PN: 210-79450; CAD_APPROVED: Yes; HEIGHT: 8.13MM; MFG_NAME01: KEYSTONE ELECTRONICS; MFG_PN01: 5011; ROHS: Yes; SILK: SDA
TP19 = TestLoop: TEST POINT PC MULTI PURPOSE BLK TH; 3D_Mechanical_Footprint_File: ftp://fcl.am.freescale.net/ALLEGRO/step/tp_th_063.STEP; AGILE_PN: 210-79450; CAD_APPROVED: Yes; HEIGHT: 8.13MM; MFG_NAME01: KEYSTONE ELECTRONICS; MFG_PN01: 5011; ROHS: Yes; SILK: VMON1_CONN
TP20 = TestLoop: TEST POINT PC MULTI PURPOSE BLK TH; 3D_Mechanical_Footprint_File: ftp://fcl.am.freescale.net/ALLEGRO/step/tp_th_063.STEP; AGILE_PN: 210-79450; CAD_APPROVED: Yes; HEIGHT: 8.13MM; MFG_NAME01: KEYSTONE ELECTRONICS; MFG_PN01: 5011; ROHS: Yes; SILK: VMON2_CONN
TP21 = TestLoop: TEST POINT PC MULTI PURPOSE BLK TH; 3D_Mechanical_Footprint_File: ftp://fcl.am.freescale.net/ALLEGRO/step/tp_th_063.STEP; AGILE_PN: 210-79450; CAD_APPROVED: Yes; HEIGHT: 8.13MM; MFG_NAME01: KEYSTONE ELECTRONICS; MFG_PN01: 5011; ROHS: Yes; SILK: VMON3_CONN
TP22 = TestLoop: TEST POINT PC MULTI PURPOSE BLK TH; 3D_Mechanical_Footprint_File: ftp://fcl.am.freescale.net/ALLEGRO/step/tp_th_063.STEP; AGILE_PN: 210-79450; CAD_APPROVED: Yes; HEIGHT: 8.13MM; MFG_NAME01: KEYSTONE ELECTRONICS; MFG_PN01: 5011; ROHS: Yes; SILK: VMON4_CONN
TP23 = TestLoop: TEST POINT PAD 30MIL DIA SMT, NO PART TO ORDER; 3D_Mechanical_Footprint_File: ftp://fcl.am.freescale.net/ALLEGRO/step/tpad_030.STEP; AGILE_PN: 211-76642; CAD_APPROVED: Yes; HEIGHT: 0.1MM; MFG_NAME01: NOTACOMPONENT; MFG_PN01: NOTACOMPONENT; ROHS: Yes; SILK: FS0B
TP24 = TestLoop: TEST POINT PAD 30MIL DIA SMT, NO PART TO ORDER; 3D_Mechanical_Footprint_File: ftp://fcl.am.freescale.net/ALLEGRO/step/tpad_030.STEP; AGILE_PN: 211-76642; CAD_APPROVED: Yes; HEIGHT: 0.1MM; MFG_NAME01: NOTACOMPONENT; MFG_PN01: NOTACOMPONENT; ROHS: Yes; SILK: GPIO1_VDDOTP
U5 = FS5600_QFN32: SUBASSEMBLY SKT 32 QFN SMT 0.5MM 577H --+IC VREG DCDC BUCK DUAL 2.7-36V 4.2-36V 3A/10A 250kHz-3MHz; AGILE_PN: 750-78486; ASSY_OPT: DNP; CAD_APPROVED: Yes; HEIGHT: 14.65MM; MFG_NAME01: SUB-ASSEMBLY; MFG_PN01: 211-80779,315-83189; ROHS: Yes
C45-C48 = CAP_POL: CAP TANT ESR=1.800 OHMS 2.2UF 10V 10% 3216-18; 3D_Mechanical_Footprint_File: ftp://fcl.am.freescale.net/ALLEGRO/step/CC3216.step; AGILE_PN: 150-30211; CAD_APPROVED: Yes; HEIGHT: 1.8MM; MFG_NAME01: AVX; MFG_PN01: TPSA225K010R1800; Package Size: 3216-18; ROHS: Yes; Tolerance: 10%; VOLTAGE: 10V
D7 = LED: LED RED SGL 20MA SMT; AGILE_PN: 370-75868; CAD_APPROVED: Yes; FPLIST: led2_2p1x1p5,led2_2p1x1p5_nsp; HEIGHT: 1.4MM; MFG_NAME01: OSRAM; MFG_PN01: LS M67K-H2L1-1-0-2-R18-Z; ROHS: Yes; SILK: PGOOD1
D8 = LED: LED RED SGL 20MA SMT; AGILE_PN: 370-75868; CAD_APPROVED: Yes; FPLIST: led2_2p1x1p5,led2_2p1x1p5_nsp; HEIGHT: 1.4MM; MFG_NAME01: OSRAM; MFG_PN01: LS M67K-H2L1-1-0-2-R18-Z; ROHS: Yes; SILK: PGOOD2
D9 = LED: LED RED SGL 20MA SMT; AGILE_PN: 370-75868; CAD_APPROVED: Yes; FPLIST: led2_2p1x1p5,led2_2p1x1p5_nsp; HEIGHT: 1.4MM; MFG_NAME01: OSRAM; MFG_PN01: LS M67K-H2L1-1-0-2-R18-Z; ROHS: Yes; SILK: FS0B
J6 J91 = CONN_HDR_8X2: CON 2X8 PLUG 2.54MM CTR 328H AU 120L; 3D_Mechanical_Footprint_File: ftp://fcl.am.freescale.net/ALLEGRO/step/hdr208_197x789_th.step; AGILE_PN: 210-80596; CAD_APPROVED: Yes; HEIGHT: 8.33MM; MFG_NAME01: TE CONNECTIVITY LTD; ROHS: Yes
J21 = CONN_HDR_2X1: CON 1X2 BANANA RED RA TH 15.3MM SP 488H AG 197L; 3D_Mechanical_Footprint_File: ftp://fcl.am.freescale.net/ALLEGRO/step/con_banana_571.STEP; AGILE_PN: 210-30144; CAD_APPROVED: Yes; HEIGHT: 12.5MM; MFG_NAME01: DELTRON EMCON LTD; MFG_PN01: 571-0500; ROHS: Yes; SILK: VBAT
J22 = CONN_HDR_2X1: CON 1X2 BANANA RED RA TH 15.3MM SP 488H AG 197L; 3D_Mechanical_Footprint_File: ftp://fcl.am.freescale.net/ALLEGRO/step/con_banana_571.STEP; AGILE_PN: 210-30144; CAD_APPROVED: Yes; HEIGHT: 12.5MM; MFG_NAME01: DELTRON EMCON LTD; MFG_PN01: 571-0500; ROHS: Yes; SILK: BIAS_IN_CON
J23 = CONN_HDR_2X1: CON 1X2 BANANA RED RA TH 15.3MM SP 488H AG 197L; 3D_Mechanical_Footprint_File: ftp://fcl.am.freescale.net/ALLEGRO/step/con_banana_571.STEP; AGILE_PN: 210-30144; CAD_APPROVED: Yes; HEIGHT: 12.5MM; MFG_NAME01: DELTRON EMCON LTD; MFG_PN01: 571-0500; ROHS: Yes; SILK: SW1OUT
J24 = CONN_HDR_2X1: CON 1X2 BANANA RED RA TH 15.3MM SP 488H AG 197L; 3D_Mechanical_Footprint_File: ftp://fcl.am.freescale.net/ALLEGRO/step/con_banana_571.STEP; AGILE_PN: 210-30144; CAD_APPROVED: Yes; HEIGHT: 12.5MM; MFG_NAME01: DELTRON EMCON LTD; MFG_PN01: 571-0500; ROHS: Yes; SILK: SW2OUT
J25 J27 J28 = CONN_HDR_2X1: CON 1X2 BANANA BLACK RA TH 15.3MM SP 492H AG 197L; AGILE_PN: 210-80576; CAD_APPROVED: Yes; HEIGHT: 12.5MM; MFG_NAME01: DELTRON EMCON LTD; MFG_PN01: 571-0100; ROHS: Yes; SILK: GND
J30 = CONN_HDR_3X1: HDR 1X3 TH 100MIL SP 330H AU 98L; AGILE_PN: 210-75442; CAD_APPROVED: Yes; HEIGHT: 8.38 MM; JUMPER[DEFAULT]: 1-2; MFG_NAME01: SAMTEC; MFG_PN01: HTSW-103-07-S-S; PRIORITY_PN: 028-00700; Package Type: HEADER; ROHS: Yes; SILK: 1:1P8V 3:3P3V; Temp Range: -55°C to +125°C; Temp_Range: -55°C to +125°C
J32 = CONN_HDR_2X1: HDR 1X2 TH 100MIL SP 338H SN 100L; 3D_Mechanical_Footprint_File: ftp://fcl.am.freescale.net/ALLEGRO/step/hdr102_338h.STEP; AGILE_PN: 210-80102; CAD_APPROVED: Yes; HEIGHT: 8.58MM; JUMPER[DEFAULT]: CLOSED; MFG_NAME01: SAMTEC; MFG_PN01: TSW-102-07-T-S; Package Size: 5.08 x 2.54 mm; ROHS: Yes; Temp Range: -55°C to +125°C
J73 = CONN_HDR_10X2: CON 2X10 PLUG 2.54MM CTR 328H AU 120L; 3D_Mechanical_Footprint_File: ftp://fcl.am.freescale.net/ALLEGRO/step/hdr210_197x989_th.step; AGILE_PN: 210-80595; CAD_APPROVED: Yes; HEIGHT: 8.33MM; MFG_NAME01: TE CONNECTIVITY LTD; ROHS: Yes
J75 = CONN_HDR_6X2: CON 2X6 PLUG 2.54MM CTR 328H AU 120L; 3D_Mechanical_Footprint_File: ftp://fcl.am.freescale.net/ALLEGRO/step/hdr206_197x589_th.step; AGILE_PN: 210-80598; CAD_APPROVED: Yes; HEIGHT: 8.33MM; MFG_NAME01: TE CONNECTIVITY LTD; ROHS: Yes
J92 = CONN_HDR_2X1: CON 1X2 BANANA RED RA TH 15.3MM SP 488H AG 197L; 3D_Mechanical_Footprint_File: ftp://fcl.am.freescale.net/ALLEGRO/step/con_banana_571.STEP; AGILE_PN: 210-30144; CAD_APPROVED: Yes; HEIGHT: 12.5MM; MFG_NAME01: DELTRON EMCON LTD; MFG_PN01: 571-0500; ROHS: Yes; SILK: VDBG
Q2-Q4 = NMOS_NX3008NBK: TRAN NMOS PWR 30V 400mA AEC-Q101 SOT23; AGILE_PN: 480-79305; CAD_APPROVED: Yes; FPLIST: SOT23_A,TO-236; HEIGHT: 1.1MM; MFG_NAME01: NEXPERIA; MFG_PN01: NX3008NBK,215; ROHS: Yes; VOLTAGE: 30V
R50 = RES: RES MF 169K 1/10W 1% AEC-Q200 0402; AGILE_PN: 470-81779; CAD_APPROVED: Yes; FPLIST: RC0402_25,RC0402_HD,0402_CC; HEIGHT: 0.40 MM; MFG_NAME01: KOA SPEER; MFG_PN01: RK73H1ETTP1693F; ROHS: Yes; Temp Coefficient - ppm/K: 100 ppm/K; Temp Range: -55C to +155C; Temp_Range: -55C to +155C; Tolerance: 1%; VOLTAGE: 50V
R52 = RES: RES MF 76.8K 1/10W 1% AEC-Q200 0402; AGILE_PN: 470-31048; CAD_APPROVED: Yes; FPLIST: RC0402_25,RC0402_HD,0402_CC; HEIGHT: 0.40 MM; MFG_NAME01: KOA SPEER; MFG_PN01: RK73H1ETTP7682F; ROHS: Yes; Temp Coefficient - ppm/K: 100 ppm/K; Temp Range: -55C to +155C; Temp_Range: -55C to +155C; Tolerance: 1%
R53 = RES: RES MF 10K 1/5W 1% AEC-Q200 0402; AGILE_PN: 470-80881; CAD_APPROVED: Yes; FPLIST: RC0402_25,RC0402_HD,0402_CC; HEIGHT: 0.4MM; MFG_NAME01: VISHAY INTERTECHNOLOGY; MFG_PN01: CRCW040210K0FKEDHP; ROHS: Yes; Temp Range: -55&#8451; to 155&#8451;; Temp_Range: -55&#8451; to 155&#8451;; Tolerance: 1%
R54 = RES: RES MF 54.9K 1/10W 1% AEC-Q200 0402; AGILE_PN: 470-76242; CAD_APPROVED: Yes; FPLIST: RC0402_25,RC0402_HD,0402_CC; HEIGHT: 0.4MM; MFG_NAME01: KOA SPEER; MFG_PN01: RK73H1ETTP5492F; ROHS: Yes; Temp Range: -55C to +155C; Temp_Range: -55C to +155C; Tolerance: 1%; VOLTAGE: 50V
R64 R67 = RES: RES MF ZERO OHM 1/16W -- AEC-Q200 0402; AGILE_PN: 470-80742; ASSY_OPT: DNP; CAD_APPROVED: Yes; FPLIST: RC0402_25,RC0402_HD,0402_CC; HEIGHT: 0.45 MM; MFG_NAME01: VISHAY INTERTECHNOLOGY; MFG_PN01: CRCW04020000Z0ED; ROHS: Yes
R69-R71 = RES: RES MF 510K 1/10W 5% 0603; AGILE_PN: 470-80477; CAD_APPROVED: Yes; FPLIST: RC0603_OV,RC0603,0603_CC; HEIGHT: 0.55MM; MFG_NAME01: YAGEO AMERICA; MFG_PN01: RC0603JR-07510KL; ROHS: Yes; Tolerance: 5%
SW3 = SW2P: SW SPST DIP SLD 25mA 24V SMD; AGILE_PN: 510-78107; CAD_APPROVED: Yes; HEIGHT: 4.5MM; MFG_NAME01: OMRON; MFG_PN01: A6S-1104-H; ROHS: Yes; VOLTAGE: 24V
TP4 = TestLoop: TEST POINT PAD 30MIL DIA SMT, NO PART TO ORDER; 3D_Mechanical_Footprint_File: ftp://fcl.am.freescale.net/ALLEGRO/step/tpad_030.STEP; AGILE_PN: 211-76642; CAD_APPROVED: Yes; HEIGHT: 0.1MM; MFG_NAME01: NOTACOMPONENT; MFG_PN01: NOTACOMPONENT; ROHS: Yes; SILK: P3V3_FRDM
TP5 = TestLoop: TEST POINT PAD 30MIL DIA SMT, NO PART TO ORDER; 3D_Mechanical_Footprint_File: ftp://fcl.am.freescale.net/ALLEGRO/step/tpad_030.STEP; AGILE_PN: 211-76642; CAD_APPROVED: Yes; HEIGHT: 0.1MM; MFG_NAME01: NOTACOMPONENT; MFG_PN01: NOTACOMPONENT; ROHS: Yes; SILK: P5V_USB
U3 U4 = MIC5205YM5_5P: IC LIN VREG LDO  1.5-15V 150MA 2.5-16V SOT23-5; AGILE_PN: 315-75304; CAD_APPROVED: Yes; HEIGHT: 1.30MM; MFG_NAME01: MICREL; MFG_PN01: MIC5205YM5; ROHS: Yes; VOLTAGE: 2.5V to +16V

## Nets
GND: C1.2 C2.2 C3.2 C4.2 C5.2 C6.2 C7.2 C8.2 C9.2 C10.2 C11.2 C13.2 C14.2 C15.2 C16.2 C17.2 C18.2 C20.2 C22.2 C24.2 C25.2 C26.2 C27.2 C32.2 C33.2 C34.2 C42.2 C43.2 C44.2 C45.2 C46.2 C47.2 C48.2 C53.2 C54.2 C55.2 CCOMP1.2 CCOMP2.2 CHF1.2 CHF2.2 D2.A J5.1 J12.5(A3) J25.1 J25.2 J27.1 J27.2 J28.1 J28.2 J29.1 J73.14 J91.12(B6) J91.14(B7) Q2.2(SOURCE) Q3.2(SOURCE) Q4.2(SOURCE) Q16.1(S1) Q16.2(S2) Q16.3(S3) R13.2 R25.2 R37.2 R38.2 R39.2 R40.2 R44.2 R51.2 R52.2 R54.2 R59.2 R63.2 R69.2 R70.2 R71.2 R72.2 R73.2 TP6.1(Pin1) TP7.1(Pin1) TP8.1(Pin1) TP9.1(Pin1) TP10.1(Pin1) TP11.1(Pin1) U3.2(GND) U4.2(GND) U5.33(EPAD)
P3V3_FRDM: J91.4(B2) J91.8(B4) TP4.1(Pin1)
P5V_USB: J91.10(B5) R45.2 R47.1 R48.1 R49.1 TP5.1(Pin1)
V7P5_REG: C48.1 J32.1 R53.1 U4.5(OUT)
VBAT: D1.1(ANODE1) D1.2(ANODE2) D2.C J21.1 J21.2
VBAT_S: C1.1 C2.1 D1.3(CATHODE) L1.1 R1.1 SW1.1(COMMON) SW2.1(COMMON)
VCC: C9.1 J93.1 U5.30(VCC)
VDDIO: C11.1 J5.3 J93.2 R8.1 R9.1 R18.1 R19.1 R28.2 R41.1 R42.1 R43.1 U5.1(VDDIO)
VDDIO_REG: J93.3 R46.1
VDDOTP: J14.7(A4) J32.2
VIN: C7.1 R1.2 R29.2 U5.32(VIN)
BIAS_IN: C8.1 J29.2 U5.29(BIAS_IN)
BIAS_IN_CON: J22.1 J22.2 J29.3
EN1: J3.2 U5.23(EN1)
EN1_IC: J3.1 J73.12
EN1_R: C4.1 J3.3 R2.1 R72.1
EN2: J4.2 U5.22(EN2)
EN2_IC: J4.1 J73.10
EN2_R: C6.1 J4.3 R6.1 R73.1
ERRMON1_IC: J6.6(B3) J14.5(A3)
ERRMON2_IC: J6.4(B2) J13.5(A3)
FCCU1_IC: J12.3(A2) J73.4
FCCU2_IC: J13.3(A2) J73.2
FS0B: C43.1 J8.2 R30.1 TP14.1(Pin1) U5.24(FS0B)
FS0B_IC: J6.14(B7) J8.3 Q4.1(GATE) R28.1 R71.1
FS0B_VIN: J8.1 R29.1
GPIO1_VDDOTP: C44.1 J14.2(B1) J14.4(B2) J14.6(B3) J14.8(B4) R44.1 TP24.1(Pin1) U5.4(GPIO1_VDDOTP)
GPIO2_VMON3: C34.1 GPIO2_VMON3.1(Pin1) J12.2(B1) J12.4(B2) J12.6(B3) J12.8(B4) U5.14(GPIO2_VMON3)
GPIO3_VMON4: C53.1 GPIO3_VMON4.1(Pin1) J13.2(B1) J13.4(B2) J13.6(B3) J13.8(B4) U5.13(GPIO3_VMON4)
GPO1_IC: J6.1(A1) J14.3(A2) R43.2
GPO2_IC: J6.3(A2) J12.1(A1) R41.2
GPO3_IC: J6.5(A3) J13.1(A1) R42.2
I2C_SCL_IC: R8.2 R64.2 R65.2 TP17.1(Pin1) U5.2(SCL)
I2C_SDA_IC: R9.2 R66.2 R67.2 TP18.1(Pin1) U5.3(SDA)
PGOOD1_IC: J73.8 Q2.1(GATE) R18.2 R69.1 TP12.1(Pin1) U5.26(PGOOD1)
PGOOD2_IC: J73.6 Q3.1(GATE) R19.2 R70.1 TP13.1(Pin1) U5.27(PGOOD2)
SW1FB: C49.2 R11.1 R59.1 U5.25(SW1FB)
SW1FB_R: C49.1 R11.2 R60.1
SW1LX1: C12.2 L3.1 L6.1 L7.1 U5.20(SW1LX1) U5.21(SW1LX2)
SW1OUT: C13.1 C14.1 C15.1 C16.1 J23.1 J23.2 L3.2 L6.2 L7.2 R60.2 TP15.1(Pin1)
SW2BOOT: C19.1 U5.12(SW2BOOT)
SW2COMP: J94.2 U5.5(SW2COMP)
SW2CSN: C37.2 R75.2 R77.1 U5.7(SW2CSN)
SW2CSP: C37.1 R12.2 R76.1 U5.8(SW2CSP)
SW2FB: C50.2 R61.1 R63.1 U5.6(SW2FB)
SW2FB_R: C50.1 R27.1 R61.2
SW2GHS: Q15.4(G) R24.1 U5.11(SW2GHS)
SW2GLS: Q16.4(G) R25.1 U5.9(SW2GLS)
SW2LX: C19.2 C51.1 L2.1 L5.1 L8.1 L9.1 L10.1 Q15.1(S1) Q15.2(S2) Q15.3(S3) Q16.5(D) R3.1 R24.2 U5.10(SW2LX)
SW2OUT: C24.1 C25.1 C26.1 C27.1 C52.2 J24.1 J24.2 L2.2 L9.2 L10.2 R27.2 R74.2 R77.2 R79.4(I2) TP16.1(Pin1)
SWIN: C17.1 C18.1 C20.1 C22.1 C54.1 C55.1 L1.2 Q15.5(D) U5.18(SW1IN1) U5.19(SW1IN2)
SYNCINMODE_IC: J5.2 R78.2 U5.31(SYNCIN_MODE)
VDIG: C10.1 U5.28(VDIG)
VMON1: C32.1 R32.2 R37.1 U5.16(VMON1) VMON1.1(Pin1)
VMON1_CONN: R32.1 TP19.1(Pin1)
VMON2: C33.1 R33.2 R38.1 U5.15(VMON2) VMON2.1(Pin1)
VMON2_CONN: R33.1 TP20.1(Pin1)
VMON3_CONN: R34.1 TP21.1(Pin1)
VMON3_R: J12.7(A4) R34.2 R39.1
VMON4_CONN: R35.1 TP22.1(Pin1)
VMON4_R: J13.7(A4) R35.2 R40.1
N17950540: J6.12(B6) R65.1
N17950546: J6.10(B5) R66.1
N17950552: J6.8(B4) R78.1
N18041286: C3.1 R2.2 SW1.2(NO)
N18053281: C5.1 R6.2 SW2.2(NO)
N18177905: C45.1 R45.1 U3.1(IN) U3.3(EN)
N18177915: C46.1 R46.2 R50.1 U3.5(OUT)
N18177949: J30.2 R50.2 U3.4(ADJ)
N18177998: J30.3 R51.1
N18178006: J30.1 R52.1
N18178603: C47.1 SW3.2(NO) U4.1(IN) U4.3(EN)
N18178669: R53.2 R54.1 U4.4(ADJ)
N18196092: J73.18 R67.1
N18196101: J73.20 R64.1
N18229657: D7.A(ANODE) R47.2
N18229660: D7.C(CATHODE) Q2.3(DRAIN)
N18229791: D8.C(CATHODE) Q3.3(DRAIN)
N18230808: D8.A(ANODE) R48.2
N18230892: D9.C(CATHODE) Q4.3(DRAIN)
N18230895: D9.A(ANODE) R49.2
N18266548: J92.1 J92.2 SW3.1(COMMON)
N18367835: L5.2 L8.2 R79.1(I1)
N18368184: R12.1 R79.2(E1)
N18377789: C51.2 R13.1
N18378672: C52.1 R3.2 R74.1 R76.2
N18406944: R75.1 R79.3(E2)
N18465771: CHF1.1 J94.1 RCOMP1.1
N18465820: CHF2.1 J94.3 RCOMP2.1
N18465826: CCOMP1.1 RCOMP1.2
N18465873: CCOMP2.1 RCOMP2.2
N18468740: C42.1 R30.2 TP23.1(Pin1)
N18472203: C12.1 U5.17(SW1BOOT)

Not connected (* = marked no-connect by the designer): J6 2(B1)* 7(A4)* 9(A5)* 11(A6)* 13(A7)* 15(A8)* 16(B8)*; J14 1(A1)*; J73 1* 3* 5* 7* 9* 11* 13* 15* 16* 17* 19*; J75 1(A1)* 2(B1)* 3(A2)* 4(B2)* 5(A3)* 6(B3)* 7(A4)* 8(B4)* 9(A5)* 10(B5)* 11(A6)* 12(B6)*; J91 1(A1)* 2(B1)* 3(A2)* 5(A3)* 6(B3)* 7(A4)* 9(A5)* 11(A6)* 13(A7)* 15(A8)* 16(B8)*

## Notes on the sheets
sheet 1
- Table of Contents
- Revision History
- 1
- TITLE
- 2
- APPENDIX JUMPER/DNP/SWITCH
- Rev
- Description
- Date
- Approved
- X1
- Initial Draft
- 3/19/2021
- Anand
- 3
- PMIC_Reference
- 4
- K82F Interface
- X1
- A070 Release
- 3/31/2021
- Anand
- A
- A085 Release
- 4/12/2021
- Anand
- 1-Updated  Q15 from
  BUK9M42-60EX(480-80263) to
  BUK9M9R5-40H(480-80266)
  2-Updated  Q16 from
  BUK9M9R5-40HX(480-80266) to
  BUK9M3R3-40H(480-80262)
- A1
- 05/06/2021
- Anand
- X-KTFS5600SKTEVM
sheet 2
- Zero ohms, jumpers and solder blobs are only for testing purposes
- User Note: 2.2 MHz operation path.
- LO NOTE:
  INPUT CAPS CLOSER TO FETS
- LO NOTE:
  Route SW2CSP and
  SW2CSN
  differentially
- User Note: Use
  BUK9M9R5-40H or
  similar for high and
  low side for 2.2 MHz
  operation. Use
  BUK9M3R3-40H/BUK9M3R3
  for HS/LS for 450kHz
  operation upto 15A.
- LO NOTE:
  Place close to FS5600
- User Note: 450 kHz operation path.
- LO NOTE:
  Place close to bottom FET
- LO NOTE:
  Place R60 close the
  output capacitors.
  Others close to FS5600
- LO NOTE:
  Place R27 close the
  output capacitors.
  Others close to FS5600
- SW2 Compensation Network
- 455KHz
- 2.22MHz
- Place close to FS5600
sheet 3
- K82F FREEDOM INTERFACE
- STATUS INDICATORS
- ON-BOARD VDDIO GENERATION
- (PTD3)
- (PTA2)
- (PTD2)
- (PTD4)
- (PTB21)
- (PTC5)
- (PTC3)
- (PTC9)
- (PTC8)
- 3P3V
- (PTC10)
- (PTC11)
- (PTD0)
- 1P8V
- Input Output Connectors
- VDDOTP Generation
sheet 4
- JUMPER TABLE
- REF DES
- JUMPER
- JUMPER[DEFAULT]
- PAGE NAME
- J94
- DEFAULT(1-2)
- 3. PMIC_Reference
- J5,J13,J12
- 1-2
- 3. PMIC_Reference
- J3,J93,J4,J8
- 2-3
- 3. PMIC_Reference
- J14
- 7-8
- 3. PMIC_Reference
- J30,J29
- 1-2
- 4. K82F Interface
- J32
- CLOSED
- 4. K82F Interface
- DNP TABLE
- REF DES
- ASSY_OPT
- PAGE NAME
- C49,C34,R13,C50,L7,R63,R12,
  R59,L8,L3,C51,CHF2,L2,L10,
  R74,C53,L5,R75
- DNP
- 3. PMIC_Reference
- R67,R64
- DNP
- 4. K82F Interface
